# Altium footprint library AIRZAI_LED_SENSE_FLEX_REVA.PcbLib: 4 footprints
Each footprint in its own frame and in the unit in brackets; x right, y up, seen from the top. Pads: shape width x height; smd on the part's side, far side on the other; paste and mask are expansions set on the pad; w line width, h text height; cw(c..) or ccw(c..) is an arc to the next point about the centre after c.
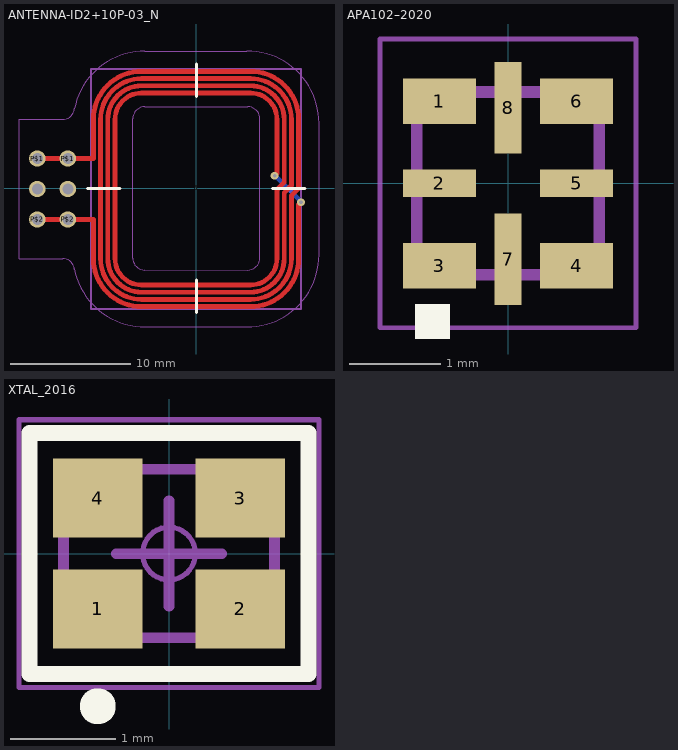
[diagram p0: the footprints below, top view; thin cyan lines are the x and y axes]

## ANTENNA-ID2+10P-03_N [mil] "ANTENNA-ID2+10P-01"
pads (7):
  rect 27.56x27.56 on Mech2: 0(0,0)
  round 54 hole 36: CON-B(-521.57,-1.97) CON-B1(-421.57,-1.97) P$1(-521.57,98.03) P$1(-421.57,98.03) P$2(-521.57,-101.97) P$2(-421.57,-101.97)
via 256.89,41.34 diameter 25.59 hole 11.81
via 343.5,-45.28 diameter 25.59 hole 11.81
Top Layer:
  lines w15.75: -521.57,-101.97 -337.6,-101.97 -337.6,-230.31 ccw(c-180.12,-230.31) -180.12,-387.8 178.15,-387.8 ccw(c178.15,-230.31) 335.63,-230.31 335.63,-53.15 344.49,-44.29 ; -521.57,98.03 -337.6,98.03 -337.6,226.38 cw(c-180.12,226.38) -180.12,383.86 178.15,383.86 cw(c178.15,226.38) 335.63,226.38 335.63,0 312.01,-23.62 312.01,-230.31 cw(c178.15,-230.31) 178.15,-364.17 -180.12,-364.17 cw(c-180.12,-230.31) -313.98,-230.31 -313.98,-1.97 -313.98,226.38 cw(c-180.12,226.38) -180.12,360.24 178.15,360.24 cw(c178.15,226.38) 312.01,226.38 312.01,9.84 288.39,-13.78 288.39,-230.31 cw(c178.15,-230.31) 178.15,-340.55 -180.12,-340.55 cw(c-180.12,-230.31) -290.35,-230.31 -290.35,-13.78 -290.35,226.38 cw(c-180.12,226.38) -180.12,336.61 178.15,336.61 cw(c178.15,226.38) 288.39,226.38 288.39,19.68 264.76,-3.94 264.76,-230.31 cw(c178.15,-230.31) 178.15,-316.93 -180.12,-316.93 cw(c-180.12,-230.31) -266.73,-230.31 -266.73,-13.78 -266.73,226.38 cw(c-180.12,226.38) -180.12,312.99 178.15,312.99 cw(c178.15,226.38) 264.76,226.38 264.76,49.21 256.89,41.34
Bottom Layer:
  lines w15.75: 256.89,43.31 344.49,-44.29
Top Overlay:
  lines w10: -356.3,0 -250,0 ; 0,-407.48 0,-301.18 ; 250,0 356.3,0 ; 0,301.18 0,407.48 0,301.18
Bottom Overlay:
  lines w10: -356.3,0 -250,0 ; 0,-407.48 0,-301.18 ; 250,0 356.3,0 ; 0,301.18 0,407.48 0,301.18
Mechanical 1:
  lines w7.87: 308.07,-10.83 319.88,0.98 ; -345.47,-395.67 343.5,-395.67 343.5,391.73 -345.47,391.73 -345.47,-395.67
Mechanical 13:
  lines w3.15: -581.69,-230.31 -581.69,226.38
Mechanical 4:
  lines w3.15: -581.69,-230.31 -438.98,-230.31 cw(c-438.98,-269.69) -399.91,-264.83 ; -581.69,226.38 -438.98,226.38 ccw(c-438.98,265.75) -399.91,260.89 ; -400.12,-263.9 ccw(c-168.31,-218.5) -168.31,-454.72 166.34,-454.72 ccw(c166.34,-218.5) 402.56,-218.5 402.56,214.57 ccw(c166.34,214.57) 166.34,450.79 -168.31,450.79 ccw(c-168.31,214.57) -399.94,260.89 ; -208.66,-228.35 ccw(c-169.29,-228.35) -169.29,-267.72 169.29,-267.72 ccw(c169.29,-228.35) 208.66,-228.35 208.66,228.35 ccw(c169.29,228.35) 169.29,267.72 -169.29,267.72 ccw(c-169.29,228.35) -208.66,228.35 -208.66,-228.35
Mechanical 5:
  text "20x20 mm" at -461.61,153.54 h40
  text "ANTENNA" at -464.17,287.52 h40
  text "Wire 0.4mm Space 0.2mm" at -464.17,222.52 h40

## APA102–2020 [mm]
pads (8):
  rect 0.8x0.5 smd: 1(-0.75,0.9) 3(-0.75,-0.9) 4(0.75,-0.9) 6(0.75,0.9)
  rect 0.8x0.3 smd: 2(-0.75,0) 5(0.75,0)
  rect 0.3x1 smd: 7(0,-0.83) 8(0,0.83)
Top Overlay:
  rectangle: -1.016,-1.702 -0.635,-1.321
Mechanical 13 (Mech13):
  lines w0.127: -1,-1 1,-1 1,1 -1,1 -1,-1
Mechanical 16:
  lines w0.05: -1.4,-1.58 1.4,-1.58 1.4,1.58 -1.4,1.58 -1.4,-1.58
3D body: height 0.94, standoff 0, extent -0.698,0.254 -0.317,0.762
3D body: height 0.94, standoff 0, extent -0.19,0.254 0.191,0.762
3D body: height 0.94, standoff 0, extent 0.318,0.254 0.699,0.762
3D body: height 0.91, standoff 0, extent -1,-1 1,1

## PCBComponent_1 [mm]

## XTAL_2016 [mm] "2.00mm x 1.60mm"
height 1
pads (4):
  rect 0.85x0.75 smd: 1(-0.675,-0.525) 2(0.675,-0.525) 3(0.675,0.525) 4(-0.675,0.525)
Top Overlay:
  circle w0.3: c-0.675,-1.448 r0.02
  lines w0.152: -1.321,-1.143 -1.321,1.143 1.321,1.143 1.321,-1.143 -1.321,-1.143
Mechanical 1:
  text ".Designator" at -0.508,-0.229 h0.51
Mechanical 13 (Mech13):
  lines w0.1: -1,-0.8 1,-0.8 ; -1,0.8 1,0.8
  lines w0.102: -1,-0.8 -1,0.8 ; 1,-0.8 1,0.8
Mechanical 15:
  circle w0.05: c0,0 r0.25
  lines w0.05: -1.422,-1.27 1.422,-1.27 1.422,0.686 1.422,1.27 -1.422,1.27 -1.422,-1.27
  lines w0.1: -0.5,0 0.5,0 ; 0,-0.5 0,0.5
3D body "User Library-XRCGB27M000F2P00R0.STEP": height 0.65, standoff 0, extent -1,-0.813 1,0.787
